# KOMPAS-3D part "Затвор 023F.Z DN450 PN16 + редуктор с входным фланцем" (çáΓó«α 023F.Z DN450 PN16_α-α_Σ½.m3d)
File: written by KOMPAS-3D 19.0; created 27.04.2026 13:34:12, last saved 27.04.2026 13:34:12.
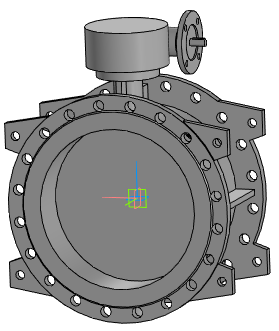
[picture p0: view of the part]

Document properties: Полное имя файла: ..\..\Затвор 023F.Z DN200-DN1600_редуктор с входным фланцем\Затвор 023F.Z DN450 PN16 + редуктор с входным фланцем.a3d

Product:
- Part/product: Затвор 023F.Z DN450 PN16 + редуктор с входным фланцем
    Масса: 245.095

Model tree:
1. Операция без истории:1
